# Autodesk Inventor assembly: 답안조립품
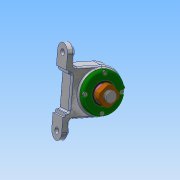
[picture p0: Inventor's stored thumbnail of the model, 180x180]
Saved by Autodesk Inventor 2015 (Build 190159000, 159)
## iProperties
Created: 2019-05
Part Number: 답안조립품
Document SubType Name: Assembly
Designer: user
Author: user
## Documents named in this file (13)
- C:\Users\user\Desktop\490504V1005\답안조립품.iam
- C:\Users\user\Desktop\490504V1005\축.ipt
- C:\Users\user\Desktop\490504V1005\앵귤러 볼 베어링 7205.ipt
- C:\Users\user\Desktop\490504V1005\칼라.ipt
- C:\Users\user\Desktop\490504V1005\커버.ipt
- C:\Users\user\Desktop\490504V1005\본체.ipt
- C:\Users\user\Desktop\490504V1005\베어링너트.ipt
- C:\Users\user\Desktop\490504V1005\오일 실 28 40 5 B.ipt
- C:\Users\user\Desktop\490504V1005\그리스니플 M6.ipt
- 그리스니플  M6.ipt
- C:\Users\user\Desktop\490504V1005\그리스니플개스킷.ipt
- C:\Users\user\Desktop\490504V1005\개스킷.ipt
- C:\Users\user\Desktop\490504V1005\볼트 M4.ipt
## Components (4 placed, 3 different names)
1. 개스킷:1
2. 개스킷:2
3. 그리스니플  M6:1
4. 그리스니플개스킷:1
